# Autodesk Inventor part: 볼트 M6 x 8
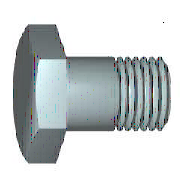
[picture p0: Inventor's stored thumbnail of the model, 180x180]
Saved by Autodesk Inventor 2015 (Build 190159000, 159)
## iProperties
Created: 2012-02
Part Number: 볼트 M6 x 8
Material: 강철, 연강
Description: 6각 머리 볼트 및 6각 머리 나사
Document SubType Name: Modeling
Standard: KS B 1002
Designer: mduedu
Standards Organization: KS
Language: ko-KR
Size Designation: C  M 6 x 12
Categories: <MemberInstance><Categories><Category DisplayName="조임쇠" InternalName="e4da775c-781d-43d5-af7c-5136215cf5a6" Mnemonic="FSTN"><Category DisplayName="볼트" InternalN
Density: 7.86 g/cm^3
Mass: 4.46616 g
Surface Area: 4.51243 cm^2
Volume: 0.568214 cm^3
Appearance: 강철
IsCustomPart: 1
Author: mduedu
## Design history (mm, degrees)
sketch "스케치1"
  geometry: L1 (0, 3)-(8, 3); L2 (8, 3)-(8, 0); L3 (8, 0)-(0, 0); L4 (-2.4, 0)-(14.4, 0) reference; L5 (0, -0.6)-(0, 3.6) reference; L6 (0, 3)-(0, 0)
  constraints: 8 end point, 3 point on line, 1 collinear
  dimensions: "d2" = 6 diameter of L1 L3 (= GD); "d59" = 8 distance between parallel lines of L2 L5 (= NLG)
revolve "본체" sketch "스케치1" stored, may be unused: angle "d12" = 90 deg
sketch "스케치2"
  geometry: L1 (0, 5.774)-(5, 2.887); L2 (5, 2.887)-(5, -2.887); L3 (5, -2.887)-(0, -5.774); L4 (0, -5.774)-(-5, -2.887); L5 (-5, -2.887)-(-5, 2.887); L6 (-5, 2.887)-(0, 5.774); L7 (-7, 0)-(7, 0) reference; L8 (0, 8.083)-(0, -8.083) reference; 2 further points
  constraints: 12 end point, 2 midpoint, 1 coincident, 1 vertical, 11 other
  dimensions: "d11" = 10 distance between parallel lines of L5 L2 (= SW)
extrude "머리" join sketch "스케치2" distance "d3" = 4 (= KOH); taper "d4" = 0 deg
revolve "모따기1" stored, may be unused: angle "d21" = 90 deg
workplane "Work Plane1"
body "Solid1"
feature "스레드" dims "d15" = 9 (= GEL), "d16" = 0
chamfer "모따기2" distance "d6" = 0.61345 (= -0.5 x SPD + 0.5 x GD); stored, may be unused: second distance "d7" = 0.61355 (computed from GUL), angle "d55" = 45 deg
sketch "스케치4"
  geometry: L1 (-3.423, 6)-(-4, 5); L2 (-1.1, 0)-(-0.234, 0); L3 (-4.753, 0)-(0.519, 0) reference; L4 (-4, 6)-(-3.423, 6); L5 (-4, 5)-(-4, 6); L6 (0, 7.2)-(0, -1.2) reference
  constraints: 8 end point, 1 parallel, 1 perpendicular, 1 point on line
  dimensions: "d65" = 10 diameter of L1.end L2 (= SW); "d67" = 30 deg angle of L1 L5 (= ANG1); "d68" = 12 diameter of L4 L2 (= 1.2 x SW); "d69" = 4 distance between parallel lines of L5 L6 (= KOH)
other parameters: "NLG" = 8 [user parameter; used in 1 equation term], "GD" = 6 (= NND) [user parameter; used in 2 equation terms], "BDM" = 6 (= NND) [user parameter], "KOH" = 4 [user parameter; used in 2 equation terms], "GEL" = 9 [user parameter; used in 1 equation term], "SW" = 10 [user parameter; used in 5 equation terms], "SPD" = 4.7731 (= NND - 1.2269 x PTC) [user parameter; used in 1 equation term], "SD2" = 6 (= NND) [user parameter], "SD" = 0 [user parameter], "ANG1" = 30 deg [user parameter; used in 1 equation term], "GAL" = 0.61345 (= 0.61345 x PTC) [user parameter], "GUL" = 0.61345 (= 0.61345 x PTC) [user parameter; used in 1 equation term], "d8" = 0, "RR" = 0.25 [user parameter], "d58" = 0, "RR1" = 0.1 [user parameter], "GD1" = 4.7731 (= THREADDIA - 1.2269 x PTC) [user parameter], "THREADDIA" = 6 [user parameter; used in 1 equation term], "TOA" = 30 deg [user parameter], "PTC" = 1 [user parameter; used in 5 equation terms], "NND" = 6 [user parameter; used in 4 equation terms], "E0" = 11.55 (= 1.155 x SW) [user parameter]
